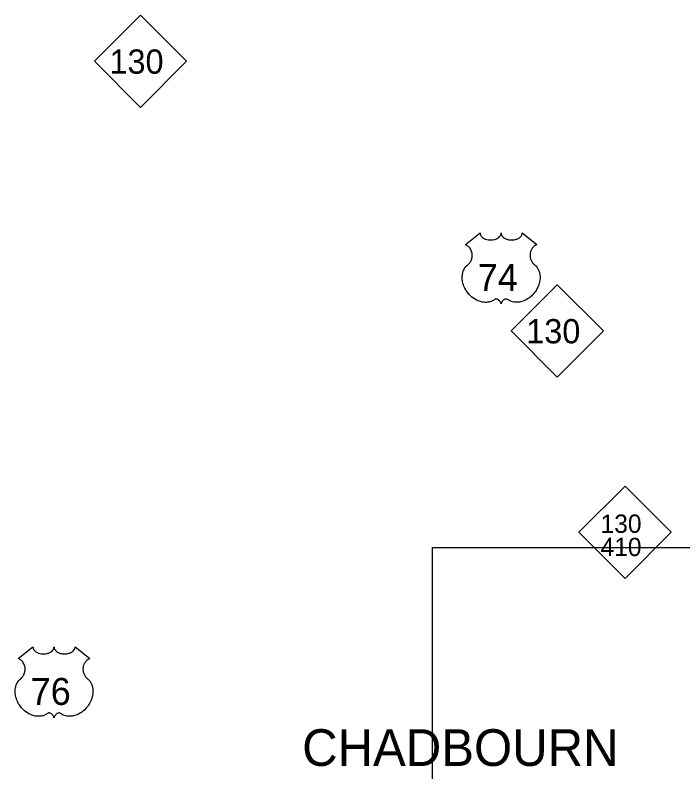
# Model space of a CAD drawing. Extents: x 5197761 to 5514561, y 1890130 to 2080942.
# Drawn here: x 5263646 to 5282925, y 2011870 to 2033715 of the extents above; entities that cross this region are included whole.
import ezdxf

# ---------------------------------------------------------------- set-up
doc = ezdxf.new("R2010")
doc.units = 0
for name, color, linetype in [('Exist Civil Demographics City Label', 7, 'Continuous'), ('Exist Road Primary NC Shield CELL', 7, 'Continuous'), ('Exist Road Primary NC Shield Number Label', 7, 'Continuous'), ('Exist Road Primary US Shield CELL', 7, 'Continuous'), ('Exist Road Primary US Shield Number Label', 7, 'Continuous'), ('Map Preparation Inset Cut Line', 7, 'Continuous')]:
    doc.layers.add(name, color=color, linetype=linetype)

msp = doc.modelspace()

# ---------------------------------------------------------------- linework, layer by layer
at = {"layer": 'Exist Road Primary NC Shield CELL'}
for points in [[(5265934, 2032383), (5267266, 2033715), (5268598, 2032383), (5267266, 2031051)], [(5277967, 2024599), (5279299, 2025931), (5280631, 2024599), (5279299, 2023267)], [(5279925, 2018786), (5281257, 2020118), (5282589, 2018786), (5281257, 2017454)]]:
    msp.add_lwpolyline(points, close=True, dxfattribs=at)
at = {"layer": 'Exist Road Primary US Shield CELL'}
for points in [[(5277070, 2027427), (5277071, 2027409), (5277075, 2027388), (5277078, 2027377), (5277088, 2027357), (5277104, 2027332), (5277127, 2027309), (5277152, 2027288), (5277169, 2027277), (5277198, 2027261), (5277231, 2027247), (5277268, 2027237), (5277305, 2027229), (5277346, 2027225), (5277386, 2027224), (5277430, 2027227), (5277478, 2027236), (5277501, 2027242), (5277525, 2027251), (5277548, 2027260), (5277574, 2027274), (5277594, 2027287), (5277610, 2027298), (5277633, 2027320), (5277651, 2027342), (5277658, 2027355), (5277665, 2027367), (5277674, 2027393), (5277676, 2027404), (5277678, 2027428), (5277679, 2027408), (5277681, 2027395), (5277685, 2027383), (5277690, 2027371), (5277699, 2027353), (5277709, 2027337), (5277728, 2027315), (5277740, 2027304), (5277750, 2027295), (5277779, 2027275), (5277813, 2027258), (5277830, 2027251), (5277847, 2027245), (5277868, 2027238), (5277891, 2027233), (5277913, 2027229), (5277935, 2027226), (5277958, 2027224), (5277977, 2027224), (5278000, 2027224), (5278022, 2027225), (5278043, 2027228), (5278068, 2027232), (5278087, 2027236), (5278112, 2027243), (5278136, 2027251), (5278156, 2027260), (5278182, 2027274), (5278204, 2027287), (5278219, 2027300), (5278238, 2027317), (5278255, 2027337), (5278266, 2027352), (5278273, 2027367), (5278280, 2027383), (5278284, 2027400), (5278286, 2027415), (5278286, 2027428), (5278711, 2027089), (5278701, 2027085), (5278678, 2027074), (5278660, 2027063), (5278631, 2027043), (5278618, 2027031), (5278606, 2027020), (5278594, 2027007), (5278584, 2026995), (5278572, 2026978), (5278561, 2026961), (5278550, 2026942), (5278542, 2026926), (5278529, 2026892), (5278522, 2026870), (5278518, 2026852), (5278513, 2026814), (5278512, 2026796), (5278512, 2026778), (5278513, 2026759), (5278515, 2026741), (5278518, 2026722), (5278521, 2026706), (5278526, 2026685), (5278534, 2026662), (5278543, 2026639), (5278563, 2026602), (5278588, 2026564), (5278606, 2026543), (5278623, 2026525), (5278649, 2026503), (5278664, 2026490), (5278680, 2026474), (5278706, 2026443), (5278717, 2026429), (5278728, 2026412), (5278738, 2026395), (5278748, 2026377), (5278756, 2026362), (5278771, 2026325), (5278782, 2026290), (5278787, 2026271), (5278795, 2026229), (5278798, 2026209), (5278801, 2026168), (5278802, 2026119), (5278798, 2026072), (5278789, 2026018), (5278782, 2025985), (5278771, 2025947), (5278760, 2025914), (5278740, 2025866), (5278723, 2025830), (5278701, 2025789), (5278685, 2025764), (5278668, 2025738), (5278645, 2025707), (5278619, 2025675), (5278588, 2025640), (5278562, 2025615), (5278529, 2025585), (5278509, 2025568), (5278481, 2025547), (5278441, 2025521), (5278403, 2025498), (5278370, 2025482), (5278341, 2025469), (5278303, 2025455), (5278240, 2025437), (5278217, 2025433), (5278190, 2025429), (5278165, 2025426), (5278140, 2025425), (5278107, 2025425), (5278074, 2025427), (5278043, 2025432), (5278011, 2025438), (5277977, 2025448), (5277946, 2025460), (5277915, 2025476), (5277862, 2025509), (5277847, 2025517), (5277839, 2025519), (5277818, 2025520), (5277799, 2025516), (5277780, 2025508), (5277768, 2025502), (5277752, 2025492), (5277740, 2025482), (5277726, 2025469), (5277716, 2025457), (5277708, 2025448), (5277693, 2025425), (5277688, 2025414), (5277682, 2025399), (5277677, 2025378), (5277671, 2025405), (5277663, 2025422), (5277654, 2025437), (5277645, 2025451), (5277630, 2025468), (5277616, 2025481), (5277600, 2025494), (5277583, 2025504), (5277570, 2025511), (5277557, 2025516), (5277542, 2025520), (5277529, 2025521), (5277519, 2025520), (5277505, 2025517), (5277485, 2025503), (5277467, 2025491), (5277447, 2025478), (5277424, 2025466), (5277406, 2025458), (5277386, 2025450), (5277362, 2025442), (5277336, 2025435), (5277309, 2025430), (5277285, 2025426), (5277260, 2025424), (5277237, 2025423), (5277213, 2025423), (5277191, 2025425), (5277165, 2025427), (5277133, 2025432), (5277106, 2025438), (5277078, 2025445), (5277049, 2025454), (5277018, 2025466), (5276980, 2025483), (5276953, 2025497), (5276910, 2025521), (5276861, 2025556), (5276823, 2025586), (5276796, 2025611), (5276755, 2025652), (5276732, 2025679), (5276694, 2025727), (5276670, 2025762), (5276655, 2025788), (5276632, 2025829), (5276620, 2025855), (5276604, 2025893), (5276591, 2025927), (5276581, 2025960), (5276575, 2025980), (5276567, 2026017), (5276562, 2026043), (5276557, 2026078), (5276555, 2026116), (5276554, 2026150), (5276555, 2026179), (5276558, 2026212), (5276564, 2026247), (5276571, 2026278), (5276577, 2026300), (5276586, 2026326), (5276598, 2026356), (5276612, 2026384), (5276625, 2026407), (5276642, 2026432), (5276659, 2026454), (5276680, 2026477), (5276703, 2026499), (5276724, 2026516), (5276748, 2026540), (5276761, 2026554), (5276777, 2026575), (5276789, 2026594), (5276799, 2026610), (5276812, 2026635), (5276819, 2026654), (5276829, 2026683), (5276834, 2026703), (5276839, 2026729), (5276842, 2026753), (5276844, 2026783), (5276843, 2026808), (5276840, 2026838), (5276834, 2026866), (5276827, 2026891), (5276817, 2026919), (5276807, 2026939), (5276791, 2026967), (5276773, 2026993), (5276754, 2027014), (5276735, 2027033), (5276717, 2027047), (5276700, 2027059), (5276678, 2027072), (5276658, 2027083), (5276644, 2027088)], [(5264162, 2015477), (5264163, 2015459), (5264167, 2015438), (5264171, 2015428), (5264180, 2015407), (5264196, 2015383), (5264219, 2015359), (5264244, 2015338), (5264261, 2015327), (5264290, 2015311), (5264323, 2015298), (5264360, 2015287), (5264397, 2015279), (5264438, 2015275), (5264479, 2015274), (5264522, 2015277), (5264570, 2015287), (5264593, 2015293), (5264618, 2015301), (5264641, 2015311), (5264666, 2015324), (5264686, 2015337), (5264702, 2015349), (5264725, 2015370), (5264743, 2015393), (5264750, 2015405), (5264757, 2015417), (5264766, 2015443), (5264768, 2015454), (5264770, 2015478), (5264772, 2015458), (5264774, 2015446), (5264777, 2015434), (5264782, 2015421), (5264791, 2015403), (5264801, 2015388), (5264820, 2015365), (5264832, 2015354), (5264843, 2015346), (5264871, 2015326), (5264905, 2015309), (5264922, 2015301), (5264939, 2015295), (5264960, 2015289), (5264983, 2015284), (5265005, 2015280), (5265028, 2015276), (5265051, 2015275), (5265069, 2015274), (5265093, 2015274), (5265114, 2015276), (5265136, 2015278), (5265160, 2015282), (5265179, 2015287), (5265205, 2015293), (5265228, 2015302), (5265248, 2015310), (5265275, 2015324), (5265296, 2015338), (5265312, 2015350), (5265330, 2015367), (5265348, 2015388), (5265358, 2015402), (5265365, 2015418), (5265372, 2015434), (5265376, 2015451), (5265378, 2015466), (5265379, 2015478), (5265804, 2015140), (5265794, 2015136), (5265771, 2015124), (5265752, 2015114), (5265723, 2015093), (5265710, 2015082), (5265698, 2015070), (5265686, 2015057), (5265676, 2015046), (5265664, 2015029), (5265653, 2015011), (5265642, 2014993), (5265634, 2014976), (5265621, 2014942), (5265615, 2014921), (5265611, 2014902), (5265606, 2014864), (5265604, 2014846), (5265604, 2014828), (5265605, 2014809), (5265607, 2014791), (5265611, 2014773), (5265614, 2014756), (5265619, 2014736), (5265626, 2014712), (5265636, 2014689), (5265655, 2014652), (5265680, 2014615), (5265698, 2014593), (5265715, 2014575), (5265742, 2014553), (5265756, 2014541), (5265772, 2014524), (5265799, 2014493), (5265810, 2014479), (5265821, 2014463), (5265831, 2014446), (5265841, 2014428), (5265849, 2014412), (5265864, 2014375), (5265874, 2014340), (5265880, 2014321), (5265887, 2014280), (5265890, 2014259), (5265894, 2014218), (5265894, 2014169), (5265890, 2014122), (5265881, 2014068), (5265874, 2014035), (5265863, 2013997), (5265852, 2013964), (5265833, 2013916), (5265815, 2013881), (5265793, 2013840), (5265778, 2013815), (5265760, 2013788), (5265738, 2013757), (5265711, 2013725), (5265680, 2013690), (5265655, 2013665), (5265622, 2013635), (5265601, 2013619), (5265573, 2013597), (5265534, 2013571), (5265495, 2013549), (5265462, 2013532), (5265433, 2013519), (5265395, 2013505), (5265333, 2013488), (5265310, 2013483), (5265283, 2013479), (5265257, 2013476), (5265233, 2013475), (5265200, 2013475), (5265167, 2013477), (5265135, 2013482), (5265103, 2013489), (5265069, 2013499), (5265038, 2013511), (5265007, 2013526), (5264955, 2013559), (5264940, 2013567), (5264931, 2013570), (5264911, 2013571), (5264892, 2013567), (5264872, 2013559), (5264860, 2013553), (5264845, 2013542), (5264832, 2013533), (5264818, 2013519), (5264808, 2013507), (5264800, 2013498), (5264785, 2013475), (5264780, 2013464), (5264775, 2013450), (5264770, 2013428), (5264763, 2013455), (5264755, 2013473), (5264746, 2013488), (5264737, 2013501), (5264722, 2013518), (5264709, 2013531), (5264693, 2013544), (5264676, 2013554), (5264662, 2013561), (5264649, 2013566), (5264634, 2013570), (5264621, 2013571), (5264611, 2013571), (5264597, 2013567), (5264578, 2013554), (5264560, 2013541), (5264540, 2013529), (5264516, 2013516), (5264499, 2013508), (5264478, 2013500), (5264454, 2013492), (5264428, 2013485), (5264401, 2013480), (5264378, 2013476), (5264352, 2013474), (5264329, 2013473), (5264305, 2013473), (5264283, 2013475), (5264257, 2013477), (5264225, 2013482), (5264199, 2013488), (5264170, 2013496), (5264142, 2013505), (5264111, 2013517), (5264072, 2013533), (5264045, 2013547), (5264003, 2013572), (5263953, 2013606), (5263915, 2013636), (5263888, 2013661), (5263848, 2013702), (5263824, 2013729), (5263787, 2013778), (5263763, 2013812), (5263747, 2013838), (5263725, 2013879), (5263712, 2013905), (5263696, 2013943), (5263683, 2013977), (5263673, 2014010), (5263667, 2014031), (5263659, 2014067), (5263654, 2014093), (5263650, 2014128), (5263647, 2014166), (5263646, 2014200), (5263647, 2014229), (5263651, 2014262), (5263656, 2014298), (5263663, 2014328), (5263669, 2014350), (5263678, 2014377), (5263690, 2014406), (5263704, 2014434), (5263718, 2014458), (5263734, 2014483), (5263751, 2014504), (5263773, 2014528), (5263795, 2014549), (5263816, 2014566), (5263841, 2014590), (5263853, 2014605), (5263869, 2014625), (5263881, 2014644), (5263891, 2014661), (5263904, 2014686), (5263912, 2014704), (5263921, 2014733), (5263926, 2014753), (5263931, 2014779), (5263935, 2014803), (5263936, 2014834), (5263935, 2014859), (5263932, 2014888), (5263926, 2014916), (5263920, 2014941), (5263909, 2014969), (5263900, 2014990), (5263883, 2015017), (5263865, 2015043), (5263846, 2015064), (5263828, 2015083), (5263810, 2015097), (5263792, 2015110), (5263771, 2015123), (5263750, 2015133), (5263737, 2015138)]]:
    msp.add_lwpolyline(points, close=True, dxfattribs=at)
at = {"layer": 'Map Preparation Inset Cut Line'}
msp.add_lwpolyline([(5275692, 2018349), (5292986, 2018349), (5292986, 2003094), (5275692, 2003094)], close=True, dxfattribs=at)

# ---------------------------------------------------------------- texts
at = {"layer": 'Exist Civil Demographics City Label'}
msp.add_text('CHADBOURN', height=1060, dxfattribs=at).set_placement((5271933, 2012041))
at = {"layer": 'Exist Road Primary NC Shield Number Label'}
for s, height, p in [('130', 700, (5266370, 2032024)), ('130', 700, (5278403, 2024240)), ('130', 530, (5280549, 2018769)), ('410', 530, (5280549, 2018097))]:
    msp.add_text(s, height=height, dxfattribs=at).set_placement(p)
at = {"layer": 'Exist Road Primary US Shield Number Label'}
for s, p in [('74', (5277001, 2025752)), ('76', (5264093, 2013802))]:
    msp.add_text(s, height=780, dxfattribs=at).set_placement(p)

doc.saveas('drawing.dxf')
